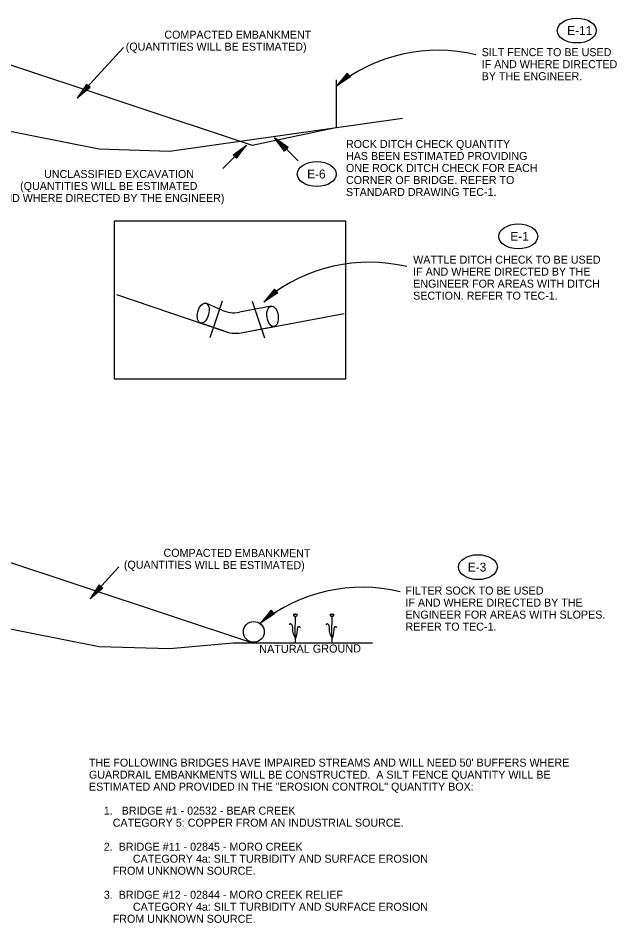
# Model space of a CAD drawing. Extents: x 1929624 to 1932072, y 596315 to 605533.
# Drawn here: x 1931112 to 1931557, y 604771 to 605448 of the extents above; entities that cross this region are included whole.
import ezdxf

# ---------------------------------------------------------------- set-up
doc = ezdxf.new("R2010")
doc.units = 0
for name, color, linetype in [('Default', 7, 'Continuous'), ('R_Border', 7, 'Continuous'), ('R_Draft', 7, 'Continuous')]:
    doc.layers.add(name, color=color, linetype=linetype)

msp = doc.modelspace()

# ---------------------------------------------------------------- linework, layer by layer
at = {"layer": 'Default'}
for p, q in [((1931052.26, 605431.37), (1931287.27, 605353.24)), ((1931190.75, 605426.41), (1931157.25, 605389.86)), ((1931358.35, 605407.12), (1931350.37, 605397.54)), ((1931358.58, 605406.86), (1931351.93, 605398.89)), ((1931358.78, 605406.63), (1931353.49, 605400.32)), ((1931358.97, 605406.42), (1931355.02, 605401.69)), ((1931359.18, 605406.16), (1931356.57, 605403.06)), ((1931360.83, 605404.34), (1931358.35, 605407.12)), ((1931360.83, 605404.34), (1931350.37, 605397.54)), ((1931360.61, 605404.57), (1931351.93, 605398.89)), ((1931360.38, 605404.8), (1931353.49, 605400.32)), ((1931360.19, 605405.01), (1931355.02, 605401.69)), ((1931359.99, 605405.25), (1931356.57, 605403.06)), ((1931359.4, 605405.93), (1931358.15, 605404.44)), ((1931359.79, 605405.51), (1931358.15, 605404.44)), ((1931163.13, 605398.8), (1931156.22, 605388.43)), ((1931165.84, 605396.34), (1931156.22, 605388.43)), ((1931163.38, 605398.61), (1931157.6, 605389.93)), ((1931165.65, 605396.53), (1931157.6, 605389.93)), ((1931163.64, 605398.37), (1931159.06, 605391.58)), ((1931165.37, 605396.75), (1931159.06, 605391.58)), ((1931163.81, 605398.15), (1931160.43, 605393.08)), ((1931165.14, 605396.96), (1931160.43, 605393.08)), ((1931164.04, 605397.98), (1931161.79, 605394.6)), ((1931164.89, 605397.18), (1931161.79, 605394.6)), ((1931165.84, 605396.34), (1931163.13, 605398.8)), ((1931164.27, 605397.75), (1931163.19, 605396.14)), ((1931164.71, 605397.43), (1931163.19, 605396.14)), ((1931287.27, 605353.24), (1931348.62, 605366.31)), ((1931311.57, 605348.78), (1931304.07, 605358.73)), ((1931314.13, 605351.38), (1931304.07, 605358.73)), ((1931265.24, 605335.85), (1931281.41, 605351.96)), ((1931273.05, 605345.99), (1931283.12, 605353.34)), ((1931273.25, 605345.76), (1931281.67, 605351.9)), ((1931275.42, 605343.58), (1931281.67, 605351.9)), ((1931275.62, 605343.39), (1931283.12, 605353.34)), ((1931321.62, 605341.52), (1931305.45, 605357.63)), ((1931311.76, 605348.97), (1931305.51, 605357.29)), ((1931313.94, 605351.15), (1931305.51, 605357.29)), ((1931313.68, 605350.9), (1931307.09, 605355.75)), ((1931311.99, 605349.23), (1931307.09, 605355.75)), ((1931312.22, 605349.45), (1931308.53, 605354.33)), ((1931313.45, 605350.73), (1931308.53, 605354.33)), ((1931313.28, 605350.51), (1931310, 605352.9)), ((1931312.45, 605349.69), (1931310, 605352.9)), ((1931275.62, 605343.39), (1931273.05, 605345.99)), ((1931273.5, 605345.51), (1931280.1, 605350.36)), ((1931273.73, 605345.34), (1931278.65, 605348.94)), ((1931273.91, 605345.12), (1931277.19, 605347.51)), ((1931274.14, 605344.9), (1931275.71, 605346.05)), ((1931274.49, 605344.48), (1931275.71, 605346.05)), ((1931274.74, 605344.3), (1931277.19, 605347.51)), ((1931274.97, 605344.06), (1931278.65, 605348.94)), ((1931275.19, 605343.84), (1931280.1, 605350.36)), ((1931313.04, 605350.29), (1931311.48, 605351.44)), ((1931312.7, 605349.86), (1931311.48, 605351.44)), ((1931311.57, 605348.78), (1931314.13, 605351.38)), ((1931304.07, 605245.27), (1931296.09, 605235.69)), ((1931304.3, 605245.01), (1931297.65, 605237.04)), ((1931304.5, 605244.78), (1931299.22, 605238.47)), ((1931304.69, 605244.57), (1931300.74, 605239.84)), ((1931304.9, 605244.31), (1931302.29, 605241.21)), ((1931305.71, 605243.39), (1931302.29, 605241.21)), ((1931305.12, 605244.08), (1931303.87, 605242.59)), ((1931305.51, 605243.65), (1931303.87, 605242.59)), ((1931306.55, 605242.49), (1931304.07, 605245.27)), ((1931185.65, 605241.36), (1931265.69, 605214.22)), ((1931306.55, 605242.49), (1931296.09, 605235.69)), ((1931306.33, 605242.72), (1931297.65, 605237.04)), ((1931306.11, 605242.95), (1931299.22, 605238.47)), ((1931305.91, 605243.16), (1931300.74, 605239.84)), ((1931278.96, 605212.68), (1931356.18, 605227.04)), ((1931052.39, 605058.51), (1931287.4, 604980.38)), ((1931187.35, 605037.19), (1931166.8, 605014.77)), ((1931172.68, 605023.71), (1931165.77, 605013.34)), ((1931175.39, 605021.25), (1931165.77, 605013.34)), ((1931172.93, 605023.52), (1931167.14, 605014.85)), ((1931175.2, 605021.44), (1931167.14, 605014.85)), ((1931173.18, 605023.28), (1931168.61, 605016.49)), ((1931174.92, 605021.66), (1931168.61, 605016.49)), ((1931173.36, 605023.06), (1931169.97, 605017.99)), ((1931174.69, 605021.88), (1931169.97, 605017.99)), ((1931173.59, 605022.89), (1931171.34, 605019.51)), ((1931174.44, 605022.1), (1931171.34, 605019.51)), ((1931175.39, 605021.25), (1931172.68, 605023.71)), ((1931173.82, 605022.67), (1931172.74, 605021.06)), ((1931174.26, 605022.34), (1931172.74, 605021.06)), ((1931301.53, 605004.77), (1931293.55, 604995.19)), ((1931304.01, 605001.99), (1931293.55, 604995.19)), ((1931301.76, 605004.51), (1931295.11, 604996.54)), ((1931303.79, 605002.22), (1931295.11, 604996.54)), ((1931301.96, 605004.28), (1931296.67, 604997.97)), ((1931303.57, 605002.45), (1931296.67, 604997.97)), ((1931302.15, 605004.07), (1931298.2, 604999.34)), ((1931303.37, 605002.66), (1931298.2, 604999.34)), ((1931302.36, 605003.81), (1931299.75, 605000.71)), ((1931303.17, 605002.89), (1931299.75, 605000.71)), ((1931302.58, 605003.58), (1931301.33, 605002.09)), ((1931302.97, 605003.15), (1931301.33, 605002.09)), ((1931304.01, 605001.99), (1931301.53, 605004.77))]:
    msp.add_line(p, q, dxfattribs=at)
for centre in [(1931426.56, 605302.62), (1931374.81, 605143.85), (1931369.74, 604900.25)]:
    msp.add_arc(centre, 121.72, 76.50197, 128.75222, dxfattribs=at)
at = {"layer": 'R_Border'}
for p, q in [((1931350.33, 605366.61), (1931350.33, 605402.3)), ((1931264.42, 605229.64), (1931252.48, 605234.89)), ((1931301.51, 605232.72), (1931277.7, 605228.1)), ((1931265.69, 605214.22), (1931248.07, 605220.18)), ((1931278.96, 605212.68), (1931303.59, 605217.25))]:
    msp.add_line(p, q, dxfattribs=at)
for points in [[(1930830.08, 605440.25), (1931067.62, 605371.32), (1931172.51, 605350.45), (1931225.36, 605348.85), (1931399.81, 605373.56)], [(1931264.74, 605236.36), (1931260.18, 605222.92), (1931255.41, 605208.86)], [(1931287.25, 605236.36), (1931291.81, 605222.92), (1931296.58, 605208.86)], [(1930830.21, 605067.4), (1931067.75, 604998.46), (1931172.64, 604977.6), (1931225.49, 604976), (1931273.1, 604980.37), (1931377.3, 604980.38)]]:
    msp.add_lwpolyline(points, dxfattribs=at)
msp.add_lwpolyline([(1931184.2, 605296.65), (1931357.2, 605296.65), (1931357.2, 605177.95), (1931184.2, 605177.95)], close=True, dxfattribs=at)
msp.add_circle((1931288.49, 604988.56), 7.8, dxfattribs=at)
for centre in [(1931273.53, 605250.17), (1931274.79, 605234.75), (1931274.79, 605234.75)]:
    msp.add_arc(centre, 22.47, 246.07844, 280.68558, dxfattribs=at)
for centre, major_axis, ratio in [((1931530.51, 605439.11), (14.6, 0), 0.638788), ((1931335.68, 605331.58), (14.6, 0), 0.638788), ((1931486.62, 605284.87), (14.6, 0), 0.638788), ((1931250.55, 605227.44), (-1.93, -7.45), 0.531792), ((1931302.55, 605224.99), (1.04, -7.73), 0.531792), ((1931456.4, 605037.06), (14.6, 0), 0.638788)]:
    msp.add_ellipse(centre, major_axis=major_axis, ratio=ratio, dxfattribs=at)
at = {"layer": 'R_Draft'}
for points in [[(1931318.32, 605001.96), (1931318.3, 605002.01), (1931318.79, 605001.3), (1931319.37, 605002.11), (1931319.8, 605001.33), (1931320.23, 605002.11), (1931320.63, 605001.34), (1931321.05, 605001.85)], [(1931345.8, 605001.97), (1931345.78, 605002.02), (1931346.27, 605001.31), (1931346.85, 605002.12), (1931347.28, 605001.34), (1931347.71, 605002.12), (1931348.11, 605001.35), (1931348.53, 605001.86)]]:
    msp.add_lwpolyline(points, dxfattribs=at)
for centre in [(1931319.66, 605001.46), (1931347.14, 605001.47)]:
    msp.add_arc(centre, 1.46, 161.12874, 15.45876, dxfattribs=at)
for points in [[(1931319.48, 605000.14), (1931319.4, 604997.03), (1931319.4, 604980.33)], [(1931346.96, 605000.15), (1931346.88, 604997.04), (1931346.88, 604980.34)], [(1931319.4, 604984.31), (1931318.45, 604986.14), (1931317.73, 604990.35), (1931315.9, 604994.56), (1931315.35, 604994.4), (1931315.18, 604993.92)], [(1931319.4, 604983.12), (1931319.95, 604983.99), (1931320.67, 604986.54), (1931321.31, 604990.74), (1931321.86, 604992.51), (1931322.35, 604992.51), (1931322.89, 604992.18), (1931322.89, 604991.71)], [(1931346.88, 604984.32), (1931345.93, 604986.15), (1931345.22, 604990.36), (1931343.39, 604994.57), (1931342.83, 604994.41), (1931342.67, 604993.93)], [(1931346.88, 604983.13), (1931347.44, 604984), (1931348.16, 604986.55), (1931348.79, 604990.75), (1931349.34, 604992.52), (1931349.83, 604992.52), (1931350.38, 604992.19), (1931350.38, 604991.72)]]:
    msp.add_spline(points, degree=3, dxfattribs=at)

# ---------------------------------------------------------------- texts
at = {"layer": 'Default'}
for s, p in [(' COMPACTED EMBANKMENT', (1931219.2, 605433.04)), ('(QUANTITIES WILL BE ESTIMATED)', (1931192.52, 605424.04)), ('SILT FENCE TO BE USED ', (1931459.23, 605419.92)), ('IF AND WHERE DIRECTED', (1931459.23, 605410.92)), ('BY THE ENGINEER. ', (1931459.23, 605401.92)), ('ROCK DITCH CHECK QUANTITY ', (1931357.55, 605351.13)), ('HAS BEEN ESTIMATED PROVIDING', (1931357.55, 605342.13)), ('ONE ROCK DITCH CHECK FOR EACH', (1931357.55, 605333.13)), ('UNCLASSIFIED EXCAVATION', (1931131.33, 605328.65)), ('(QUANTITIES WILL BE ESTIMATED', (1931113.38, 605319.65)), ('CORNER OF BRIDGE. REFER TO', (1931357.55, 605324.13)), ('STANDARD DRAWING TEC-1. ', (1931357.55, 605315.13)), ('IF AND WHERE DIRECTED BY THE ENGINEER)', (1931086.82, 605310.65)), ('WATTLE DITCH CHECK TO BE USED', (1931407.89, 605264.46)), ('IF AND WHERE DIRECTED BY THE', (1931407.89, 605255.46)), ('ENGINEER FOR AREAS WITH DITCH ', (1931407.89, 605246.46)), ('SECTION. REFER TO TEC-1.', (1931407.89, 605237.46)), ('FILTER SOCK TO BE USED', (1931402.1, 605016.5)), ('IF AND WHERE DIRECTED BY THE', (1931402.1, 605007.5)), ('ENGINEER FOR AREAS WITH SLOPES. ', (1931402.1, 604998.5)), ('REFER TO TEC-1.', (1931402.1, 604989.5))]:
    msp.add_text(s, height=6, dxfattribs=at).set_placement(p)
for s, height, rotation, p in [('COMPACTED EMBANKMENT', 6, 359.82713, (1931220.82, 605044.83)), ('(QUANTITIES WILL BE ESTIMATED)', 6, 359.82713, (1931191.12, 605035.92)), ('NATURAL GROUND', 6.075, 0.38559, (1931292.53, 604972.64))]:
    msp.add_text(s, height=height, rotation=rotation, dxfattribs=at).set_placement(p)
at = {"layer": 'R_Border'}
for s, p in [('E-11', (1931523.29, 605435.83)), ('E-6', (1931328.41, 605328.3)), ('E-1', (1931480.71, 605281.6)), ('E-3', (1931448.79, 605033.79))]:
    msp.add_text(s, height=6.663, rotation=360, dxfattribs=at).set_placement(p)
for s, p in [("THE FOLLOWING BRIDGES HAVE IMPAIRED STREAMS AND WILL NEED 50' BUFFERS WHERE", (1931164.95, 604887.6)), ('GUARDRAIL EMBANKMENTS WILL BE CONSTRUCTED.  A SILT FENCE QUANTITY WILL BE', (1931164.95, 604878.6)), ('ESTIMATED AND PROVIDED IN THE "EROSION CONTROL" QUANTITY BOX:', (1931164.95, 604869.6)), ('     1.   BRIDGE #1 - 02532 - BEAR CREEK ', (1931164.95, 604851.6)), ('        CATEGORY 5: COPPER FROM AN INDUSTRIAL SOURCE.', (1931164.95, 604842.6)), ('     2.  BRIDGE #11 - 02845 - MORO CREEK', (1931164.95, 604824.6)), ('    CATEGORY 4a: SILT TURBIDITY AND SURFACE EROSION', (1931188.95, 604815.6)), ('        FROM UNKNOWN SOURCE.', (1931164.95, 604806.6)), ('     3.  BRIDGE #12 - 02844 - MORO CREEK RELIEF', (1931164.95, 604788.6)), ('    CATEGORY 4a: SILT TURBIDITY AND SURFACE EROSION', (1931188.95, 604779.6)), ('        FROM UNKNOWN SOURCE.', (1931164.95, 604770.6))]:
    msp.add_text(s, height=6, dxfattribs=at).set_placement(p)

doc.saveas('drawing.dxf')
